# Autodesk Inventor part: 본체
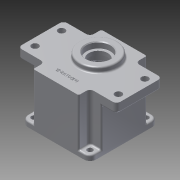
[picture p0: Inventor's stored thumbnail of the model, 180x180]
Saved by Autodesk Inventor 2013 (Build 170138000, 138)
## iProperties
Created: 2015-07
Part Number: 본체
Material: 알루미늄 6061
Document SubType Name: Modeling
Designer: user
Density: 1 g/cm^3
Author: user
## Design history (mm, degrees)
sketch "스케치1"
  geometry: L1 (-37, 45)-(37, 45); L2 (45, 37)-(45, -37); L3 (37, -45)-(-37, -45); L4 (-45, -37)-(-45, 37); A1 r 8 centre (-37, 37) between (-37, 45) and (-45, 37); A2 r 8 centre (-37, -37) between (-45, -37) and (-37, -45); A3 r 8 centre (37, -37) between (37, -45) and (45, -37); A4 r 8 centre (37, 37) between (45, 37) and (37, 45); 6 further points
  constraints: 8 end point, 8 point on circle, 8 tangent, 6 point on line, 4 centre point, 3 equal radius, 2 midpoint, 2 parallel, 1 horizontal, 1 horizontal alignment, 1 perpendicular, 1 vertical alignment
  dimensions: "d0" = 90 distance of point (45, -45) point (-45, -45); "d1" = 90 distance of point (45, 45) point (45, -45); "d2" = 8 radius of A1
extrude "돌출1" new body sketch "스케치1" distance "d3" = 70; taper "d4" = 0 deg
sketch "스케치2"
  geometry: L1 (37, 45)-(-37, 45) reference; L2 (45, -37)-(45, 37) reference; L3 (65, 25)-(65, -25); L4 (-65, -25)-(-65, 25); L5 (-60, 30)-(-38, 30); L6 (35, 30)-(60, 30); L7 (-33, 35)-(-33, 43); L8 (30, 43)-(30, 35); L9 (30, -35)-(30, -43); L10 (60, -30)-(35, -30); L11 (-35, -30)-(-60, -30); L12 (-37, -45)-(37, -45) reference; L13 (-31, 45)-(28, 45); L14 (-30, -35)-(-30, -43); L15 (-28, -45)-(28, -45); A1 r 5 centre (-38, 35) between (-38, 30) and (-33, 35); A2 r 5 centre (35, 35) between (30, 35) and (35, 30); A3 r 5 centre (35, -35) between (35, -30) and (30, -35); A4 r 5 centre (-35, -35) between (-30, -35) and (-35, -30); A5 r 5 centre (60, 25) between (65, 25) and (60, 30); A6 r 5 centre (60, -25) between (60, -30) and (65, -25); A7 r 5 centre (-60, -25) between (-65, -25) and (-60, -30); A8 r 5 centre (-60, 25) between (-60, 30) and (-65, 25); A9 r 2 centre (28, 43) between (30, 43) and (28, 45); A10 r 2 centre (-31, 43) between (-31, 45) and (-33, 43); A11 r 2 centre (-28, -43) between (-30, -43) and (-28, -45); A12 r 2 centre (28, -43) between (28, -45) and (30, -43); 12 further points
  constraints: 27 tangent, 24 end point, 24 point on circle, 14 point on line, 12 centre point, 9 equal radius, 8 parallel, 3 perpendicular, 3 vertical alignment, 2 collinear, 2 horizontal, 2 horizontal alignment, 2 midpoint
  dimensions: "d15" = 5 radius of A1; "d121" = 2 radius of A10; "d122" = 2 radius of A11; "d123" = 15 distance between parallel lines of L2 L9; "d124" = 75 distance between parallel lines of L2 L14; "d125" = 78 distance between parallel lines of L2 L7; "d126" = 110 distance between parallel lines of L2 L4; "d127" = 15 distance between parallel lines of L1 L5; "d128" = 20 distance between parallel lines of L3 L2; "d129" = 0 distance from line of point (0, 45) L1; "d130" = 15 distance from line of point (0, 30) L1; "d131" = 75 distance from line of point (-30, 0) L2
extrude "돌출2" join sketch "스케치2" distance "d16" = 12; taper "d17" = 0 deg
sketch "스케치3"
  geometry: L1 (37, 45)-(-37, 45) reference; L2 (-45, -30)-(-45, -37) reference; L3 (-37, -45)-(37, -45) reference; L4 (45, -37)-(45, -30) reference; L5 (-35, 30)-(-45, 30); L6 (35, 30)-(45, 30); L7 (30, 35)-(30, 45); L8 (30, -35)-(30, -45); L9 (35, -30)-(45, -30); L10 (-30, -35)-(-30, -45); L11 (-35, -30)-(-45, -30); L12 (-30, 35)-(-30, 45); L13 (-45, 45)-(-30, 45); L14 (30, 45)-(45, 45); L15 (45, -45)-(30, -45); L16 (-30, -45)-(-45, -45); L17 (-45, -45)-(-45, -30); L18 (-45, 30)-(-45, 45); L19 (45, 45)-(45, 30); L20 (45, -30)-(45, -45); A1 r 8 centre (-37, 37) between (-37, 45) and (-45, 37) reference; A2 r 5 centre (-60, 25) between (-60, 30) and (-65, 25) reference; A3 r 5 centre (-60, -25) between (-65, -25) and (-60, -30) reference; A4 r 8 centre (-37, -37) between (-45, -37) and (-37, -45) reference; A5 r 8 centre (37, -37) between (37, -45) and (45, -37) reference; A6 r 8 centre (37, 37) between (45, 37) and (37, 45) reference; A7 r 5 centre (-35, 35) between (-35, 30) and (-30, 35); A8 r 5 centre (35, 35) between (30, 35) and (35, 30); A9 r 5 centre (35, -35) between (35, -30) and (30, -35); A10 r 5 centre (-35, -35) between (-30, -35) and (-35, -30); 2 further points
  constraints: 32 end point, 18 tangent, 9 perpendicular, 8 parallel, 8 point on circle, 4 centre point, 3 equal radius, 2 horizontal, 1 point on line
  dimensions: "d19" = 15 distance between parallel lines of L4 L8; "d20" = 75 distance between parallel lines of L2 L7; "d21" = 15 distance between parallel lines of L2 L10; "d22" = 90 distance from line of point (60, 30) L12; "d23" = 5 radius of A7
extrude "돌출3" cut sketch "스케치3" distance "d24" = 63; taper "d25" = 0 deg
node "작업 평면1"
sketch "스케치4"
  geometry: L1 (0, 0)-(0, 11); C1 r 25 at (0, 11)
  constraints: 2 end point, 1 centre point, 1 coincident, 1 vertical
  dimensions: "d27" = 11 distance of L1.start L1.end; "d28" = 50 diameter of C1
extrude "돌출4" join sketch "스케치4" stored distance "d29" = 63; taper "d30" = 0 deg
sketch "스케치5"
  geometry: C1 r 40 at (0, 0); 1 further point
  constraints: 1 centre point, 1 coincident
  dimensions: "d31" = 80 diameter of C1
extrude "돌출5" cut sketch "스케치5" distance "d32" = 9; taper "d33" = 0 deg
sketch "스케치6"
  geometry: L1 (45, 30)-(45, -30) reference; L2 (45, -30)-(35, -30) reference; L3 (30, -35)-(30, -45) reference; L4 (30, -45)-(-30, -45) reference; L5 (-30, -45)-(-30, -35) reference; L6 (-35, -30)-(-45, -30) reference; L7 (-45, -30)-(-45, 30) reference; L8 (-45, 30)-(-35, 30) reference; L9 (-30, 35)-(-30, 45) reference; L10 (-30, 45)-(30, 45) reference; L11 (30, 45)-(30, 35) reference; L12 (35, 30)-(45, 30) reference; L13 (0, 0)-(35, 0); C1 r 40 at (0, 0) reference; C2 r 40 at (0, 0) reference; A1 r 5 centre (35, -35) between (35, -30) and (30, -35) reference; A2 r 5 centre (-35, -35) between (-30, -35) and (-35, -30) reference; A3 r 5 centre (-35, 35) between (-35, 30) and (-30, 35) reference; A4 r 5 centre (35, 35) between (30, 35) and (35, 30) reference; A5 r 4 centre (24.749, 24.749) between (22.208, 27.839) and (27.839, 22.208); A6 r 3.5 centre (19.986, 30.542) between (22.208, 27.839) and (23.427, 31.18); A7 r 3.5 centre (30.542, 19.986) between (31.18, 23.427) and (27.839, 22.208); A8 r 3.5 centre (-30.542, 19.986) between (-27.839, 22.208) and (-31.18, 23.427); A9 r 4 centre (-24.749, 24.749) between (-27.839, 22.208) and (-22.208, 27.839); A10 r 3.5 centre (-19.986, 30.542) between (-23.427, 31.18) and (-22.208, 27.839); A11 r 3.5 centre (-19.986, -30.542) between (-22.208, -27.839) and (-23.427, -31.18); A12 r 4 centre (-24.749, -24.749) between (-22.208, -27.839) and (-27.839, -22.208); A13 r 3.5 centre (-30.542, -19.986) between (-31.18, -23.427) and (-27.839, -22.208); A14 r 3.5 centre (30.542, -19.986) between (27.839, -22.208) and (31.18, -23.427); A15 r 4 centre (24.749, -24.749) between (27.839, -22.208) and (22.208, -27.839); A16 r 3.5 centre (19.986, -30.542) between (23.427, -31.18) and (22.208, -27.839); A17 r 39 centre (0, 0) between (-23.427, -31.18) and (23.427, -31.18); A18 r 39 centre (0, 0) between (31.18, -23.427) and (31.18, 23.427); A19 r 39 centre (0, 0) between (23.427, 31.18) and (-23.427, 31.18); A20 r 39 centre (0, 0) between (-31.18, 23.427) and (-31.18, -23.427)
  constraints: 32 point on circle, 16 centre point, 5 tangent, 2 coincident, 2 end point, 1 horizontal, 41 other
  dimensions: "d36" = 4 radius of A5; "d37" = 3.5 radius of A6; "d38" = 3.5 radius of A7; "d42" = 360 deg dimension on L13.start A6.centre (derived); "d44" = 39 radius of A17; "d45" = 10 distance from line of L13.end L1; "d46" = 13.82038 distance from line of A7.start L1
extrude "돌출6" cut sketch "스케치6" distance "d47" = 52; taper "d48" = 0 deg
sketch "스케치10"
  geometry: C1 r 25 at (0, 0) reference; 1 further point
hole "구멍3" sketch "스케치10" at (0, 0) diameter "d71" = 25; stored, may be unused: countersink angle "d75" = 90 deg, drill point angle "d77" = 0 deg; dims "d72" = 6, "d73" = 32, "d74" = 8, "d76" = 13
sketch "스케치11"
  geometry: L1 (-55, 17.5)-(55, 17.5); L2 (55, 17.5)-(55, -17.5); L3 (55, -17.5)-(-55, -17.5); L4 (-55, -17.5)-(-55, 17.5); 7 further points
  constraints: 8 end point, 4 coincident, 2 midpoint, 2 parallel, 1 horizontal, 1 horizontal alignment, 1 perpendicular, 1 vertical alignment
  dimensions: "d78" = 110 distance of L2.end L3.end; "d79" = 35 distance of L1.end L2.end
hole "구멍4" sketch "스케치11" at (-55, 17.5), (-55, -17.5), (55, -17.5), (55, 17.5) diameter "d80" = 9; stored, may be unused: countersink angle "d84" = 90 deg, drill point angle "d86" = 0 deg; dims "d81" = 6, "d82" = 32, "d83" = 8, "d85" = 13
sketch "스케치12"
  geometry: L1 (-37, 37)-(37, 37); L2 (37, 37)-(37, -37); L3 (37, -37)-(-37, -37); L4 (-37, -37)-(-37, 37); C1 r 40 at (0, 0) reference; 6 further points
  constraints: 8 end point, 4 coincident, 2 midpoint, 2 parallel, 1 horizontal, 1 horizontal alignment, 1 perpendicular, 1 vertical alignment
  dimensions: "d87" = 74 distance of L2.end L3.end; "d88" = 74 distance of L1.end L2.end
hole "구멍5" sketch "스케치12" at (-37, 37), (-37, -37), (37, -37), (37, 37) diameter "d89" = 7; stored, may be unused: countersink angle "d93" = 90 deg, drill point angle "d95" = 0 deg; dims "d90" = 6, "d91" = 32, "d92" = 8, "d94" = 13
sketch "스케치13"
  geometry: A1 r 4 centre (24.749, 24.749) between (22.208, 27.839) and (27.839, 22.208) reference; A2 r 4 centre (24.749, -24.749) between (27.839, -22.208) and (22.208, -27.839) reference; A3 r 4 centre (-24.749, -24.749) between (-22.208, -27.839) and (-27.839, -22.208) reference; A4 r 4 centre (-24.749, 24.749) between (-27.839, 22.208) and (-22.208, 27.839) reference
hole "구멍6" sketch "스케치13" at (-24.749, 24.749), (24.749, -24.749), (-24.749, -24.749), (24.749, 24.749) diameter "d96" = 3.459; stored, may be unused: countersink angle "d100" = 90 deg, drill point angle "d102" = 118 deg; dims "d97" = 12, "d98" = 4, "d99" = 2, "d101" = 15
fillet "모깎기1" dims "d103" = 2
fillet "모깎기2" dims "d104" = 2
fillet "모깎기3" dims "d105" = 2
fillet "모깎기4" dims "d106" = 2
sketch "스케치14"
  geometry: L1 (-28, -45)-(28, -45) reference; L2 (0, -45)-(0, -30); 2 further points
  constraints: 2 end point, 1 coincident, 1 midpoint, 1 perpendicular, 1 other
  dimensions: "d111" = 15 distance of L2.start L2.end
feature "엠보싱1" sketch "스케치14" dims "d0" = 90, "d1" = 90, "d2" = 8, "d112" = 0.5, "d113" = 0
chamfer "모따기1" distance "d114" = 1; stored, may be unused: second distance "d115" = 2, angle "d116" = 45 deg
fillet "모깎기9" dims "d117" = 0.3
fillet "모깎기10" dims "d118" = 3.5
fillet "모깎기11" dims "d119" = 2
sketch "스케치15"
  geometry: L1 (-30, -43)-(-30, -35) reference; L2 (-35, -30)-(-60, -30) reference; L3 (-65, -25)-(-65, 25) reference; L4 (-60, 30)-(-35, 30) reference; L5 (-30, 35)-(-30, 43) reference; L6 (-28, 45)-(28, 45) reference; L7 (30, 43)-(30, 35) reference; L8 (35, 30)-(60, 30) reference; L9 (65, 25)-(65, -25) reference; L10 (60, -30)-(35, -30) reference; L11 (30, -35)-(30, -43) reference; L12 (28, -45)-(-28, -45) reference; L13 (0, 0)-(0, 11); L14 (0, 0)-(0, -20); C1 r 4.5 at (-55, -17.5) reference; C2 r 4.5 at (55, 17.5) reference; C3 r 4.5 at (55, -17.5) reference; C4 r 4.5 at (-55, 17.5) reference; A1 r 5 centre (-35, -35) between (-30, -35) and (-35, -30) reference; A2 r 5 centre (-60, -25) between (-65, -25) and (-60, -30) reference; A3 r 5 centre (-60, 25) between (-60, 30) and (-65, 25) reference; A4 r 5 centre (-35, 35) between (-35, 30) and (-30, 35) reference; A5 r 2 centre (-28, 43) between (-28, 45) and (-30, 43) reference; A6 r 2 centre (28, 43) between (30, 43) and (28, 45) reference; A7 r 5 centre (35, 35) between (30, 35) and (35, 30) reference; A8 r 5 centre (60, 25) between (65, 25) and (60, 30) reference; A9 r 5 centre (60, -25) between (60, -30) and (65, -25) reference; A10 r 5 centre (35, -35) between (35, -30) and (30, -35) reference; A11 r 2 centre (28, -43) between (28, -45) and (30, -43) reference; A12 r 2 centre (-28, -43) between (-30, -43) and (-28, -45) reference; A13 r 20.5 centre (0, 11) between (11.115, -6.225) and (-11.115, -6.225); A14 r 14 centre (0, -20) between (-10.493, -10.732) and (10.493, -10.732); A15 r 3 centre (-12.742, -8.746) between (-10.493, -10.732) and (-11.115, -6.225); A16 r 3 centre (12.742, -8.746) between (11.115, -6.225) and (10.493, -10.732); A17 r 1.5 centre (29.836, -19.238) between (28.818, -20.34) and (31.096, -20.05) reference; A18 r 37 centre (0, 0) between (31.096, -20.05) and (31.096, 20.05) reference; A19 r 1.5 centre (29.836, 19.238) between (31.096, 20.05) and (28.818, 20.34) reference; A20 r 6 centre (24.749, 24.749) between (20.34, 28.818) and (28.818, 20.34) reference; A21 r 1.5 centre (19.238, 29.836) between (20.34, 28.818) and (20.05, 31.096) reference; A22 r 37 centre (0, 0) between (20.05, 31.096) and (-20.05, 31.096) reference; A23 r 1.5 centre (-19.238, 29.836) between (-20.05, 31.096) and (-20.34, 28.818) reference; A24 r 6 centre (-24.749, 24.749) between (-28.818, 20.34) and (-20.34, 28.818) reference; A25 r 1.5 centre (-29.836, 19.238) between (-28.818, 20.34) and (-31.096, 20.05) reference; A26 r 37 centre (0, 0) between (-31.096, 20.05) and (-31.096, -20.05) reference; A27 r 1.5 centre (-29.836, -19.238) between (-31.096, -20.05) and (-28.818, -20.34) reference; A28 r 6 centre (-24.749, -24.749) between (-20.34, -28.818) and (-28.818, -20.34) reference; A29 r 1.5 centre (-19.238, -29.836) between (-20.34, -28.818) and (-20.05, -31.096) reference; A30 r 37 centre (0, 0) between (-20.05, -31.096) and (20.05, -31.096) reference; A31 r 1.5 centre (19.238, -29.836) between (20.05, -31.096) and (20.34, -28.818) reference; A32 r 6 centre (24.749, -24.749) between (28.818, -20.34) and (20.34, -28.818) reference
  constraints: 8 point on circle, 4 centre point, 4 end point, 4 tangent, 2 coincident, 1 collinear, 1 perpendicular
  dimensions: "d132" = 11 distance of L13.start L13.end; "d133" = 20 distance of L13.start L14.end; "d134" = 20.5 radius of A13; "d135" = 14 radius of A14; "d136" = 3 radius of A15; "d137" = 3 radius of A16
extrude "돌출8" join sketch "스케치15" distance "d138" = 7; taper "d139" = 0 deg
sketch "스케치16"
  geometry: A1 r 20.5 centre (0, 11) between (11.115, -6.225) and (-11.115, -6.225) reference; 1 further point
hole "구멍7" sketch "스케치16" at (0, 11) diameter "d140" = 25; stored, may be unused: countersink angle "d144" = 90 deg, drill point angle "d146" = 0 deg; dims "d141" = 12, "d142" = 35, "d143" = 10, "d145" = 15
sketch "스케치17"
  geometry: A1 r 14 centre (0, -20) between (-10.493, -10.732) and (10.493, -10.732) reference; 1 further point
hole "구멍8" sketch "스케치17" at (0, -20) diameter "d147" = 19; stored, may be unused: countersink angle "d151" = 90 deg, drill point angle "d153" = 0 deg; dims "d148" = 12, "d149" = 22, "d150" = 7, "d152" = 8
fillet "모깎기12" dims "d154" = 2
fillet "모깎기13" dims "d155" = 2
fillet "모깎기14" dims "d156" = 0.3
chamfer "모따기2" distance "d157" = 1; stored, may be unused: second distance "d158" = 2, angle "d159" = 45 deg
node "솔리드1"
node "절단 모서리 투영1"
node "절단 모서리 투영3"
other parameters: "d26" = 77, "d39" = 78
